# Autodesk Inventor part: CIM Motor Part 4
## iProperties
Created: 2010-01
Part Number: CIM Motor Part 4
Document SubType Name: Modeling
Designer: cmcfadden
Density: 1 g/cm^3
Author: cmcfadden
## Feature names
1. Extrusion1
2. Extrusion2
